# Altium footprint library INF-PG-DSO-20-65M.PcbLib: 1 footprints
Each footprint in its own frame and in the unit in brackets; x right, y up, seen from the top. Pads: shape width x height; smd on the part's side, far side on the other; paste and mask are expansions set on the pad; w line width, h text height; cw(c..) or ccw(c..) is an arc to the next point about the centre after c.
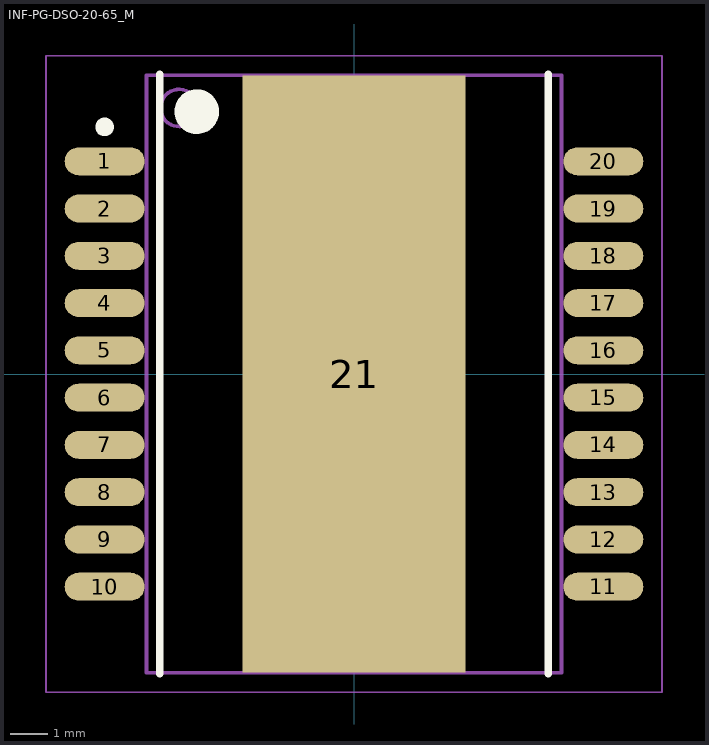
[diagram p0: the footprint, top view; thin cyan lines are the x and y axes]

## INF-PG-DSO-20-65_M [mm] "SOP, 20-Leads, Body 15.9x11mm, Pitch 1.27mm, Thermal Pad 16.05x6mm, IPC Low Density"
height 3.5
pads (21):
  oval 2.15x0.75 smd: 1(-6.7,5.715) 2(-6.7,4.445) 3(-6.7,3.175) 4(-6.7,1.905) 5(-6.7,0.635) 6(-6.7,-0.635) 7(-6.7,-1.905) 8(-6.7,-3.175) 9(-6.7,-4.445) 10(-6.7,-5.715) 11(6.7,-5.715) 12(6.7,-4.445) 13(6.7,-3.175) 14(6.7,-1.905) 15(6.7,-0.635) 16(6.7,0.635) 17(6.7,1.905) 18(6.7,3.175) 19(6.7,4.445) 20(6.7,5.715)
  rect 6x16.05 smd: 21(0,0)
Top Overlay:
  circle w0.25: c-6.7,6.64 r0.125
  circle w0.6: c-4.225,7.05 r0.3
  lines w0.2: -5.225,-8.05 -5.225,8.05 ; 5.225,-8.05 5.225,8.05
Mechanical 13:
  circle w0.1: c-4.7,7.15 r0.5
  lines w0.1: -5.575,-8.025 -5.575,8.025 5.575,8.025 5.575,-8.025 -5.575,-8.025
Mechanical 15:
  lines w0.05: -8.275,-8.55 -8.275,8.55 8.275,8.55 8.275,-8.55 -8.275,-8.55
  lines w0.1: -0.5,0 0.5,0 ; 0,-0.5 0,0.5
3D body: height 3.5, standoff 0, extent -5.575,-8.025 5.575,8.025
